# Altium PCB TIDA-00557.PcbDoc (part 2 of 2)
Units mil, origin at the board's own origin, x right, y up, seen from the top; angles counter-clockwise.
Board outline 3556 x 3500 mil, 2 copper layers (Top Layer, Bottom Layer), stack 62 mil thick; 145 components, 107 nets, 402 pads, 185 vias.
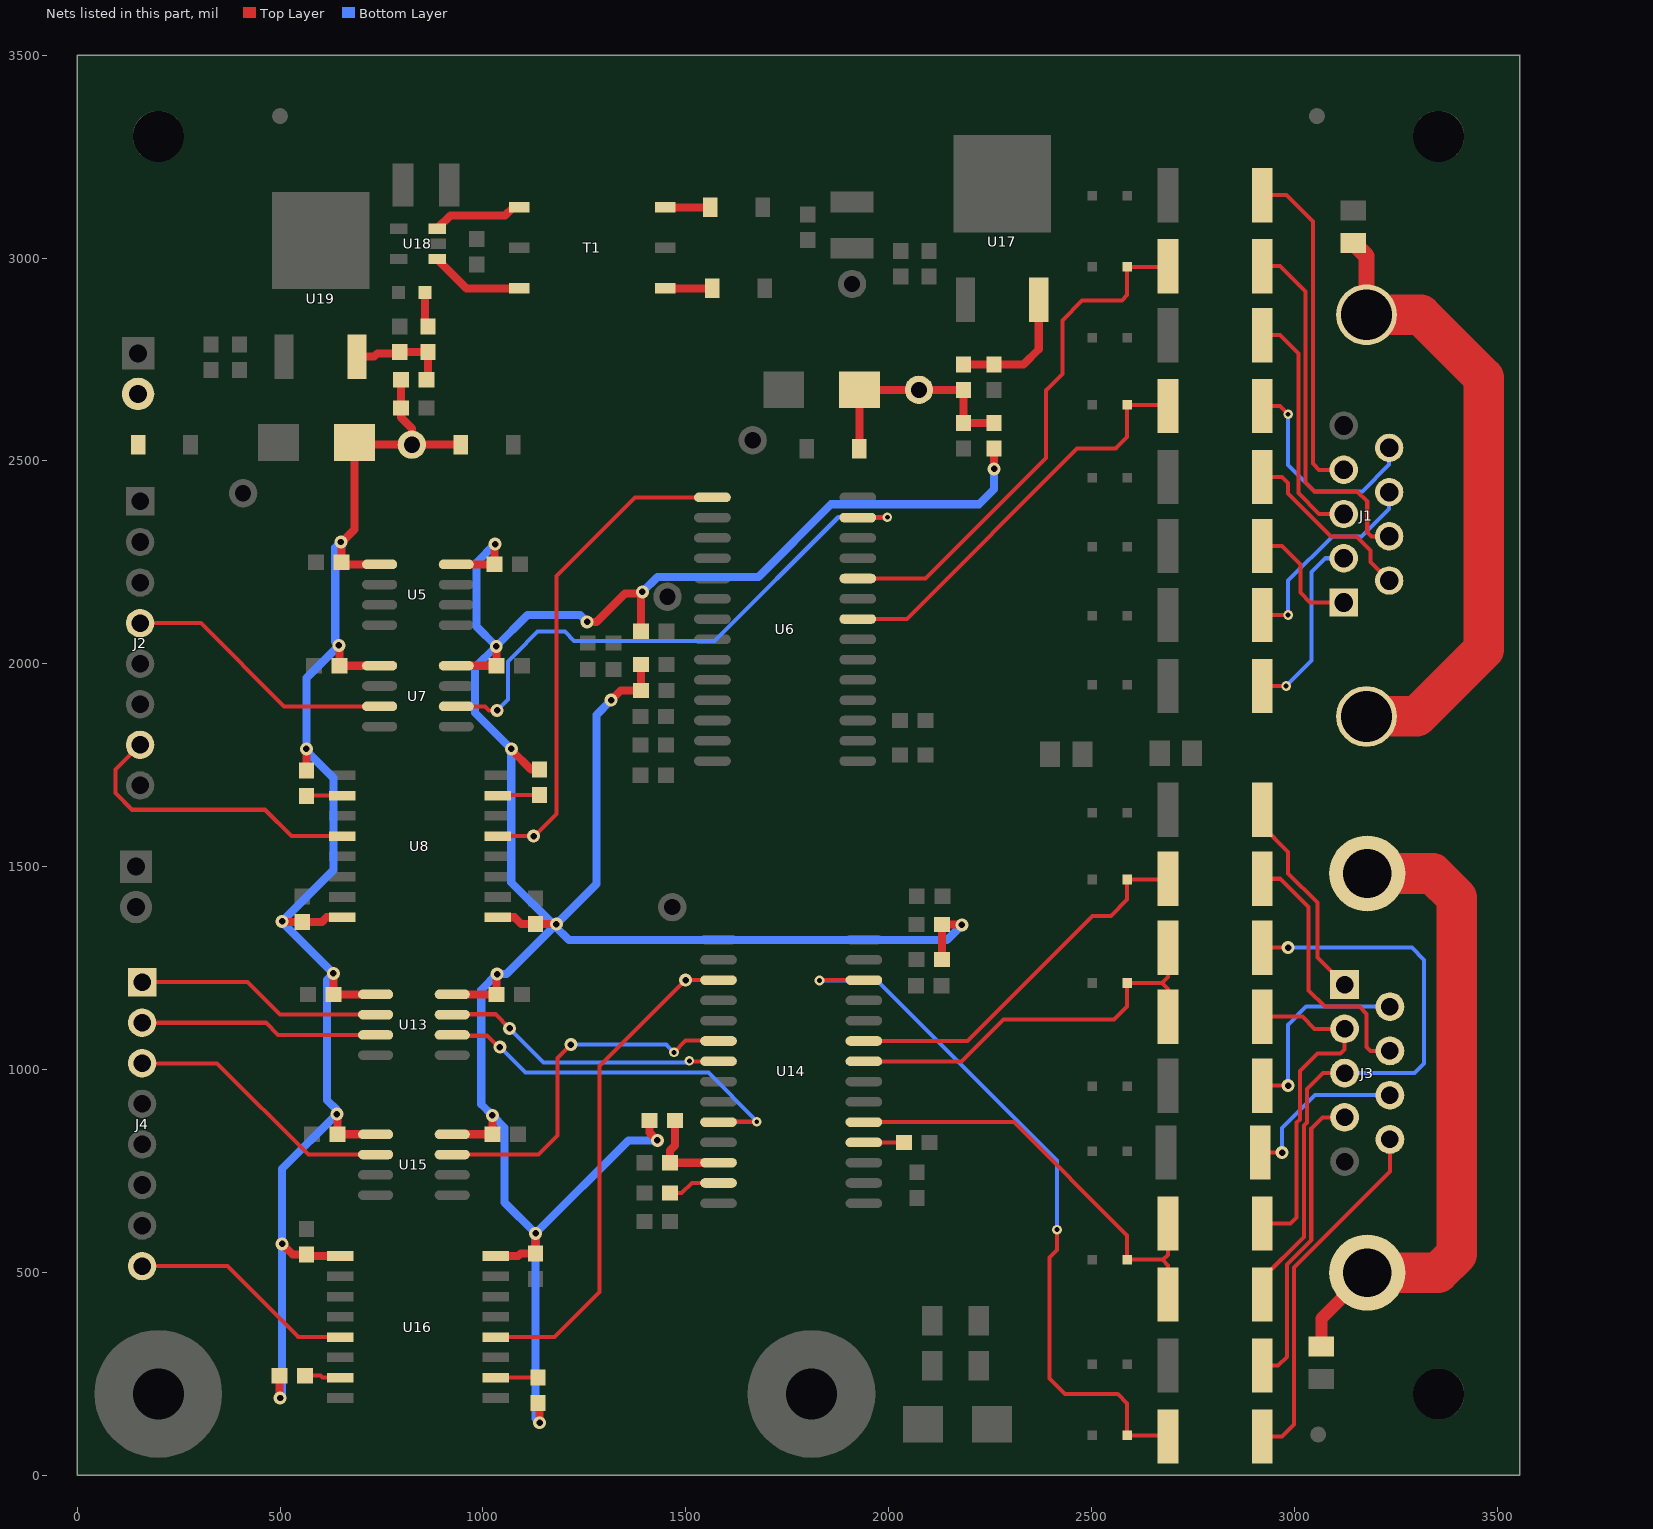
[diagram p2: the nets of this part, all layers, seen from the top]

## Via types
v1: diameter 32, hole 16, Top Layer to Bottom Layer, 163 vias
v2: diameter 24, hole 12, Top Layer to Bottom Layer, 22 vias

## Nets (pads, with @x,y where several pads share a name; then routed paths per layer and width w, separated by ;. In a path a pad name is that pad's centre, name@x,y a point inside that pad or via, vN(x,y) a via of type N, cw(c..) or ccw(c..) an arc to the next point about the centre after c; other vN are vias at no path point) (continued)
NetC18_1: C18.1 U14.4 | length 99.4
  Top Layer w10: U14.4@1939.13,820 C18.1@2038.5,820
NetC19_1: C19.1 U14.27 | length 129.7
  Top Layer w10: C19.1@1461.5,695 1490,695 1515,720 U14.27@1580.87,720
NetC20_1: C20.1 R50.1 U14.26 | length 228.3
  Top Layer w20: R50.1@1473.5,874 1473.5,812.5 1461.5,800.5 C20.1@1461.5,770 U14.26@1580.87,770
NetC27_1: C27.1 C31.1 D23.1 FB1.2 R17.1 TP1.1 | length 558.9
  Top Layer w20: D23.1@1927.47,2530 1928.5,2531.04 C27.1@1928.5,2675 TP1.1@2075,2675 FB1.2@2185,2675 C31.1@2185,2592.99 R17.1@2260,2592.99
NetC28_1: C28.1 FB1.1 U17.3 | length 322.3
  Top Layer w20: FB1.1@2185,2737.99 C28.1@2260,2737.99 2332.99,2737.99 2370.16,2775.16 U17.3@2370.16,2896.89
NetC34_1: C34.1 FB2.1 R18.2 U19.3 | length 249.6
  Top Layer w20: U19.3@690.16,2756.89 731.89,2756.89 740,2765 791.5,2765 C34.1@795,2768.5 R18.2@865,2768.5 865,2703.5 FB2.1@861.5,2700
NetD1_2: D1.2 T1.6 | length 110.7
  Top Layer w20: T1.6@1449.84,3125 D1.2@1560.53,3125
NetD2_2: D2.2 T1.4 | length 115.7
  Top Layer w20: T1.4@1449.84,2925 D2.2@1565.53,2925
NetD3_2: D3.2 J5.2 | length 0.8
  Top Layer w20: D3.2@150,2540.53 D3.2@150.53,2540
NetD4_2: D4.2 R18.1 | length 86.6
  Top Layer w20: D4.2@857.48,2915 857.48,2839.02 R18.1@865,2831.5
NetJ1_1: J1.1 R19.2 | length 299.4
  Top Layer w10: R19.2@2921.14,2290 2970,2290 3015,2245 3015,2175 3039,2151 J1.1@3122,2151
NetJ1_2: J1.2 R21.2 | length 459
  Top Layer w10: R21.2@2921.14,1945 2949.73,1945 v2(2980,1945)
  Bottom Layer w10: v2(2980,1945) 3043,2008 3043,2226 3077,2260 J1.2@3122,2260
NetJ1_3: J1.3 R23.2 | length 585.4
  Top Layer w10: R23.2@2921.14,2810 2965,2810 3010,2765 3010,2420.46 3061.46,2369 J1.3@3122,2369
NetJ1_4: J1.4 R25.2 | length 831
  Top Layer w10: R25.2@2921.14,3155 2981,3155 3046,3090 3046,2493 3061,2478 J1.4@3122,2478
NetJ1_6: J1.6 R20.2 | length 449.5
  Top Layer w10: R20.2@2921.14,2460 2970,2460 2985,2445 2985,2420 3091,2314 3153,2314 3187.89,2279.11 3187.89,2251.11 J1.6@3234,2205
NetJ1_7: J1.7 R22.2 | length 908.6
  Top Layer w10: R22.2@2921.14,2980 2965,2980 3028,2917 3028,2447 3050,2425 3155,2425 3180,2400 3180,2324 3190,2314 J1.7@3234,2314
NetJ1_8: J1.8 R24.2 | length 512.2
  Top Layer w10: R24.2@2921.14,2120 v2(2985,2120)
  Bottom Layer w10: v2(2985,2120) 2985,2205 3094,2314 3166.12,2314 3234,2381.88 J1.8@3234,2423
NetJ1_9: J1.9 R26.2 | length 541.5
  Top Layer w10: R26.2@2921.14,2635 2965,2635 v2(2985,2615)
  Bottom Layer w10: v2(2985,2615) 2985,2490 3050,2425 3168.12,2425 3234,2490.88 J1.9@3234,2532
NetJ1_10: J1.10 J1.11 L1.1 | length 1570.8
  Top Layer w40: L1.1@3146,3037 3178,3005 J1.10@3178,2860
  Top Layer w100: J1.11@3178,1870 3302,1870 3467,2035 3467,2705 3312,2860 J1.10@3178,2860
NetJ3_1: J3.1 R31.1 | length 514.9
  Top Layer w10: R31.1@2921.14,1640 2921.14,1599.86 2985,1536 2985,1483 3057,1411 3057,1276.19 J3.1@3124.08,1209.11
NetJ3_4: J3.4 R35.1 | length 750.5
  Top Layer w10: R35.1@2921.14,270 2960,270 2981.65,291.65 2981.65,519.19 3042,579.54 3042,854 3069.95,881.95 J3.4@3124.08,881.95
NetJ3_6: J3.6 R32.1 | length 483.2
  Top Layer w10: R32.1@2921.14,960 v1(2985,960)
  Bottom Layer w10: v1(2985,960) 2985,1110 3029.58,1154.58 J3.6@3235.89,1154.58
NetJ3_7: J3.7 R33.1 | length 658.7
  Top Layer w10: R33.1@2921.14,1470 2965,1470 3035,1400 3035,1195 3075.42,1154.58 3160.42,1154.58 3178,1137 3178,1055 3187.47,1045.53 J3.7@3235.89,1045.53
NetJ3_8: J3.8 R34.1 | length 413.5
  Top Layer w10: R34.1@2916.14,795 v1(2970,795)
  Bottom Layer w10: v1(2970,795) 2970,855 3051.47,936.47 J3.8@3235.89,936.47
NetJ3_9: J3.9 R36.1 | length 891.4
  Top Layer w10: R36.1@2921.14,95 2970,95 2999.65,124.65 2999.65,511.74 3235.89,747.98 J3.9@3235.89,827.42
NetJ3_10: J3.10 J3.11 L2.1 | length 1592.7
  Top Layer w30: L2.1@3067,317 3067,386.09 J3.11@3179.98,499.07
  Top Layer w100: J3.11@3179.98,499.07 3355.07,499.07 3401,545 3401,1423 3341.07,1482.93 J3.10@3179.98,1482.93
NetR7_1: R7.1 U8.7 | length 115.9
  Top Layer w10: U8.7@1024.13,1676.5 R7.1@1140,1676.5
NetR8_1: R8.1 U8.10 | length 101.5
  Top Layer w10: R8.1@565,1673.5 566.5,1675 U8.10@665.87,1675
NetR15_1: R15.1 U16.10 | length 117.1
  Top Layer w10: U16.10@1019.13,240 1135.5,240 R15.1@1136,240.5
NetR16_1: R16.1 U16.7 | length 101.4
  Top Layer w10: R16.1@561.5,245 600,245 605,240 U16.7@660.87,240
NetT1_1: T1.1 U18.3 | length 224.5
  Top Layer w20: U18.3@887.24,3072.4 919.84,3105 1055,3105 1075,3125 T1.1@1090,3125
NetT1_3: T1.3 U18.1 | length 232.8
  Top Layer w20: U18.1@887.24,2997.6 959.84,2925 T1.3@1090,2925
RI_IN: D13.1 R26.1 U6.8 | length 1031.3
  Top Layer w10: U6.8@1924.13,2110 2045,2110 2465,2530 2560,2530 2588.31,2558.31 D13.1@2588.31,2637.99 2685.87,2637.99 R26.1@2688.86,2635
RI_IN_1: U6.15 U8.5 | length 1235
  Top Layer w10: U8.5@1024.13,1575 v1(1125,1575) ; v1@1119,1581 1133,1581 1181,1629 1181,2216 1375,2410 U6.15@1565.87,2410
RI_OUT: D22.1 R36.2 U14.12 | length 1820.1
  Top Layer w10: v2(1830,1219) 1831,1220 U14.12@1939.13,1220 ; v2(2415,605) 2415,554.47 2397,536.47 2397,238 2435,200 2565,200 2588.31,176.69 D22.1@2588.31,97.99 2685.87,97.99 R36.2@2688.86,95
  Bottom Layer w10: v2(1830,1219) 1971,1219 2415,775 v2(2415,605)
RI_OUT_1: U14.17 U16.12 | length 1252.3
  Top Layer w10: U16.12@1019.13,340 1176.54,340 1288,451.46 1288,1008 v1(1500,1220) U14.17@1580.87,1220
RIIN: J2.7 U8.12 | length 759.8
  Top Layer w10: J2.7@155,1800 94,1739 94,1681.46 135.46,1640 462.83,1640 527.83,1575 U8.12@665.87,1575
RIOUT: J4.8 U16.5 | length 573.4
  Top Layer w10: J4.8@160,515 370,515 545,340 U16.5@660.87,340
RTS_IN: D20.1 R33.2 U14.9 | length 944.5
  Top Layer w10: U14.9@1939.13,1070 2195,1070 2503,1378 2548,1378 2588.31,1418.31 D20.1@2588.31,1467.99 2686.85,1467.99 R33.2@2688.86,1470
RTS_IN_1: U14.20 U15.7 | length 899.4
  Top Layer w10: U15.7@924.49,790 1137,790 1184,837 1184,1028 v1(1217,1061) ; v2(1471,1042) 1500,1071 U14.20@1579.87,1071
  Bottom Layer w10: v1(1217,1061) 1452,1061 v2(1471,1042)
RTS_OUT: D9.1 R22.1 U6.10 | length 1299.9
  Top Layer w10: U6.10@1924.13,2210 2091.46,2210 2388,2506.54 2388,2674 2428.46,2714.46 2428.46,2846.46 2477,2895 2575,2895 2588.31,2908.31 D9.1@2588.31,2977.99 2686.85,2977.99 R22.1@2688.86,2980
RTS_OUT_1: U6.13 U7.6 | length 1410.8
  Top Layer w10: U7.6@934.49,1895 1005,1895 1015,1885 v1(1035,1885) ; U6.13@1924.13,2361 v2(1997,2361)
  Bottom Layer w10: v1(1035,1885) 1062,1912 1062,2005.53 1080,2023.53 1080,2024 1135,2079 1202,2079 1225,2056 1571,2056 1876,2361 v2(1997,2361)
RTSIN: J4.3 U15.2 | length 668.7
  Top Layer w10: J4.3@160,1015 345,1015 570,790 U15.2@735.51,790
RTSOUT: J2.4 U7.3 | length 675.4
  Top Layer w10: J2.4@155,2100 305,2100 510,1895 U7.3@745.51,1895
RX_IN: J3.2 R27.2 R29.2 | length 853.8
  Top Layer w10: R27.2@2921.14,620 2991,620 3006,635 3006,868.91 3014,876.91 3014,996 3057.43,1039.43 3114.43,1039.43 3124.08,1049.08 J3.2@3124.08,1100.06 3049.94,1100.06 3020,1130 R29.2@2921.14,1130
RX_IN_1: U13.7 U14.21 | length 709.8
  Top Layer w10: U13.7@924.49,1135 927.49,1138 929.49,1136 1031,1136 v1(1066,1101) ; v2(1509,1021) 1510,1020 U14.21@1580.87,1020
  Bottom Layer w10: v1(1066,1101) 1150,1017 1505,1017 v2(1509,1021)
RX_IN_T: D16.1 R29.1 R30.1 U14.8 | length 1030.9
  Top Layer w10: U14.8@1939.13,1020 2180,1020 2283,1123 2556,1123 2588.31,1155.31 D16.1@2588.31,1212.99 2674.01,1212.99 ; R29.1@2688.86,1130 2688.86,1198.14 2674.01,1212.99 ; R30.1@2688.86,1300 2688.86,1227.84 2674.01,1212.99
RXIN: J4.1 U13.2 | length 608.6
  Top Layer w10: J4.1@160,1215 420,1215 500,1135 U13.2@735.51,1135
TX_OUT: J3.3 R28.2 R30.2 | length 1533.3
  Top Layer w10: R28.2@2921.14,445 2921.14,484.14 3024,587 3024,861.46 3032,869.46 3032,952 3071,991 J3.3@3124.08,991 ; R30.2@2921.14,1300 v1(2985,1300)
  Bottom Layer w10: v1(2985,1300) 3290,1300 3320,1270 3320,1015 3296,991 J3.3@3124.08,991
TX_OUT_1: U13.6 U14.24 | length 934.9
  Top Layer w10: U13.6@924.49,1085 926.49,1083 1010,1083 1038,1055 v1(1042,1055) ; U14.24@1580.87,870 1581.87,871 v2(1675,871)
  Bottom Layer w10: v1(1042,1055) 1105,992 1556,992 1675,873 v2(1675,871)
TX_OUT_T: D17.1 R27.1 R28.1 U14.5 | length 1101.7
  Top Layer w10: U14.5@1939.13,870 2309,870 2588.31,590.69 D17.1@2588.31,530.99 2675.01,530.99 ; R28.1@2686.85,442.99 R28.1@2688.86,445 2688.86,517.14 2675.01,530.99 ; R27.1@2688.86,620 2688.86,542.86 2676.99,530.99 2675.01,530.99
TXOUT: J4.2 U13.3 | length 587.9
  Top Layer w10: J4.2@160,1115 465,1115 495,1085 U13.3@735.51,1085
VCC1: C1.1 C4.1 C10.1 C12.1 C16.1 C21.1 C35.1 C36.1 D5.1 FB2.2 R8.2 R16.2 TP3.1 U5.1 U7.1 U8.16 U13.1 U15.1 U16.1 | length 4092.2
  Top Layer w20: R16.2@498.5,245 498.5,191.5 v1(500,190) ; v1(505,570) 531.5,543.5 C21.1@565,543.5 568.5,540 U16.1@660.87,540 ; v1(505,1365) 506.5,1363.5 C10.1@555,1363.5 603.5,1363.5 615,1375 U8.16@665.87,1375 ; R8.2@565,1736.5 v1(565,1790) ; v1(631.5,1236.5) C12.1@631.5,1185 U13.1@735.51,1185 ; v1(640,890) 641.5,888.5 C16.1@641.5,840 U15.1@735.51,840 ; v1(645,2045) 646.5,2043.5 C4.1@646.5,1995 U7.1@745.51,1995 ; U5.1@745.51,2245 656.5,2245 C1.1@651.5,2250 651.5,2298.5 683.5,2330.51 C35.1@683.5,2545 688.5,2540 TP3.1@825,2540 ; FB2.2@798.5,2700 C36.1@798.5,2630 798.5,2606.5 825,2580 TP3.1@825,2540 ; D5.1@945.53,2540 TP3.1@825,2540
  Bottom Layer w20: v1(500,190) 505,195 v1(505,570) 505,755 v1(640,890) 640,900 616,924 616,1221 v1(631.5,1236.5) 505,1362.99 v1(505,1365) 631.5,1491.5 631.5,1718.42 565,1784.92 v1(565,1790) 565,1965 v1(645,2045) 636,2054 636,2286 v1(650,2300)
VCC2: C2.1 C5.1 C11.1 C13.1 C17.1 C22.1 R1.2 R2.2 R7.2 R9.2 R10.2 R15.2 R17.2 R50.2 R51.1 U5.8 U7.8 U8.1 U13.8 U15.8 U16.16 | length 7489.5
  Top Layer w20: U15.8@924.49,840 C17.1@1023.5,840 v1(1023.5,886.5) ; U13.8@924.49,1185 C13.1@1033.5,1185 1033.5,1233.5 v1(1035,1235) ; U7.8@934.49,1995 C5.1@1033.5,1995 1033.5,2042.5 v1(1033,2043) ; U5.8@934.49,2245 C2.1@1028.5,2245 1028.5,2293.5 v1(1030,2295) ; U16.16@1019.13,540 1087,540 1093.5,546.5 C22.1@1130,546.5 v1(1130,596) ; U8.1@1024.13,1375 1078,1375 1094.5,1358.5 C11.1@1130,1358.5 1180.5,1358.5 v1(1181,1358) ; v1(1070,1790) 1070,1787.8 1118.3,1739.5 R7.2@1140,1739.5 ; R15.2@1136,177.5 1140,173.5 v1(1140,129) ; v1(1257,2103) 1280,2103 1350.5,2173.5 1389.5,2173.5 R2.2@1389.5,2080 ; v1(1316,1910) 1340,1934 R51.1@1389.5,1934 R1.2@1389.5,1998 ; R50.2@1410.5,874 1410.5,844.5 v1(1430,825) ; R9.2@2131.5,1271 R10.2@2131.5,1357 2180,1357 v1(2181,1356) ; v1(2260,2480) R17.2@2260,2530
  Bottom Layer w20: v1(1030,2295) 984,2249 984,2092 v1(1033,2043) ; v1(1140,129) 1130,139 v1(1130,596) ; v1@1173,1358 1070,1461 v1(1070,1790) 981,1879 981,1991 v1(1033,2043) ; v1@1177,1354 1212,1319 2144,1319 v1(2181,1356) ; v1(1257,2103) 1240,2120 1110,2120 v1(1033,2043) ; v1(1316,1910) 1280,1874 1280,1457 1058,1235 v1(1035,1235) 996,1196 996,914.01 v1(1023.5,886.5) 1053.76,856.24 1053.76,672.24 v1(1130,596) ; v1(1393,2177) 1430,2214 1679,2214 1858,2393 2223,2393 2260,2430 v1(2260,2480) ; v1(1430,825) 1359,825 v1(1130,596)
pads on no net: FID1.1 FID2.1 FID3.1 H2.1 H3.1 H5.0 H6.0 H7.0 H8.0 H9.1 H10.0 LBL1.0 U6.20 U14.16

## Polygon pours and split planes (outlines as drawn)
GND1 on Top Layer "Top Layer-No Net" (solid, remove dead copper, pour order 26): 96,1555 211,1555 216,1550 216,1346 205,1335 88,1335 79,1344 79,1550 84,1555
NetD3_2 on Top Layer "Top Layer-No Net" (solid, remove dead copper, pour order 18): 90,2709 191,2709 199,2701 199,2491 193,2485 92,2485 78,2499 78,2698 89,2709
+5V on Top Layer "Top Layer-No Net" (solid, pour order 21): 480,2815 535,2815 545,2805 545,2695 535,2685 515,2665 445,2665 402.43,2665 371.74,2635 330,2593.26 330,2500 315,2485 265,2485 245,2505 245,2731.26 256.3,2742.56 260.24,2746.5 268.11,2746.5 461.5,2746.5 470,2755 470,2805
GND1 on Top Layer "Top Layer-No Net" (solid, pour order 24): 499,3245 827,3245 840,3232 840,3210 840,3135 820,3115 820,2980 810,2970 730,2970 725,2965 725,2925 715,2915 490,2915 475,2930 475,2950 475,3221
VCC1 on Top Layer "Top Layer-No Net" (solid, remove dead copper, pour order 22): 760.2,2727.2 819.8,2727.2 823,2724 828,2719 828,2601 838,2591 849,2591 963,2591 974,2580 974,2455 968,2449 629,2449 614,2464 614,2609 633,2628 637,2628 748,2628 758,2638 758,2701 758,2725
+6V_VDC on Top Layer "Top Layer-No Net" (solid, remove dead copper, pour order 16): 1664,3155 1664,2858 1696,2826 2256,2826 2268,2838 2268,2963 2254,2977 2252,2977 2097,2977 1978,2977 1975,2980.84 1975,2997 1975,3051 1962,3064 1759,3064 1756,3067 1735,3088 1735,3134 1735,3157 1728,3164 1727,3165 1674,3165
GND_EARTH on Top Layer "Top Layer-No Net" (solid, remove dead copper, pour order 27): 2135,410 2135,75 2130,70 1885,70 1674,70 1650,94 1650,394 1671,415 2135,415
GND3 on Top Layer "Top Layer-No Net" (solid, remove dead copper, pour order 28): 2452.5,1845 2452.5,1705 2462.5,1695 2677.5,1695 2692.5,1710 2692.5,1845 2682.5,1855 2462.5,1855 2452.5,1845
GND3 on Top Layer "Top Layer-No Net" (solid, remove dead copper, pour order 30): 2195,420 2195,60 2225,30 2420,30 2440,50 2440,400 2415,425 2200,425 2195,420
GND2 on Top Layer "Top Layer-No Net" (solid, remove dead copper, pour order 29): 1630.83,2441.3 1630.83,579.17 1690,520 2685,520 2840,365 3495,365 3529,399 3529,3402 3501,3430 1890,3430 1845,3385 1845,3121.85 1856.85,3110 1980,3110 2010,3080 2010,3005 2015,3000 2270,3000 2300,2970 2300,2570 2290,2560 1835,2560 1810,2585 1810,2720 1795,2735 1650,2735 1630,2715
GND2 on Bottom Layer "Top Layer-No Net" (solid, remove dead copper, pour order 17): 1404,3467 3471,3467 3514,3424 3514,375 3501,362 2727,362 2706,383 2706,3219 2691,3234 2405,3234 2375,3204 2375,506 2368,499 1648,499 1589,440 1589,110.45 1533.55,55 937,55 916.68,75.32 916.68,2281.68 917,2282 916.68,2282.32 916.68,2288.13 966.55,2338 1222,2338 1354.03,2470.03 1354.03,3417.03
GND3 on Bottom Layer "Top Layer-No Net" (solid, remove dead copper, pour order 20): 3152,284 3162,274 3162,183 3151,172 2331,172 2305,198 2305,375 2314,384 2611,384 2651,344 2651,290 2657,284
GND3 on Bottom Layer "Top Layer-No Net" (solid, remove dead copper, pour order 23): 2434,3129 2444,3119 3170,3119 3180,3129 3180,3212 3171,3221 2441,3221 2434,3214
GND1 on Bottom Layer "Top Layer-No Net" (solid, remove dead copper, pour order 25): 78,3445 1081,3445 1152,3374 1152,2491 1104,2443 844,2443 811,2410 809,2408 758,2357 758,55 66,55 55,66 55,3422
GND3 on Bottom Layer "Top Layer-No Net" (solid, remove dead copper, pour order 19): 2433,3160 2456.49,3183.49 2484.96,3183.49 2650.51,3183.49 2669,3165 2672,3162 2672,3041 2672,95 2657,80 2650,73 2514,73 2216,73 2208,81 2208,91 2208,394 2208,409 2218,419 2223,424 2326,424 2327,425 2395,425 2417,425 2427,435 2427,3090 2427,3154

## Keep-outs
Keep-Out Layer:
  lines w6: 10,10 3546,10 3546,3490 10,3490 10,10
  text ".Layer_Name" at 577,-858.49 h60
Multi-Layer:
  circle w10: c3356,200 r100
  circle w10: c203,3301 r100
  circle w10: c3352,3304 r100

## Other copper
Top Layer:
  pour cut-out: 3193,3249 3222.66,3249 3228,3243.66 3228,3224 3197,3224 3193,3228
  pour cut-out: 2416.96,1695 2416.96,1574.96 2386,1544 2386,799 2460,725 2460,390 2482,368 3498,368 3508,378 3508,1591 3501.7,1597.3 3072.7,1597.3 2982,1688 2982,1735 2976,1741 2711.57,1741 2692.5,1721.93 2648.27,1721.93 2648.27,1695.28 2647.99,1695
  pour cut-out: 1969,2269 1969,1901 2594,1901 2639,1856 2712,1856 2723,1845 3037,1845 3038,1844 3038,1780 3065,1753 3509,1753 3509,2981 3207,2981 3200,2988 3200,3248 2626,3248 2626,3198 2400,3198 2400,2485 2184,2269
  pour cut-out: 2424,1695.53 2423.47,1695 2442,1695 2442,1860.55 2440.55,1862 2424,1862
  pour cut-out: 2723,1845 2723,1741 2708,1741 2708,1845
  pour cut-out: 1869,1348 1868,1347 1868,656 1877,647 1982,647 2026.5,691.5 2026.5,1318.5 1997,1348
  pour cut-out: 1851,2432 1850,2431 1850,1740 1859,1731 1947,1731 1956,1740 1956,2421 1945,2432
  pour cut-out: 1616.7,1347.64 1647.36,1347.64 1655,1340 1655,550 1609.2,550
  pour cut-out: 2400,3198 2627,3198 2627,3065.23 2400,3065.23
  text ".Layer_Name" at 577,-858.49 h60
Bottom Layer:
  pour cut-out: 2420,3249 3211,3249 3211,3084 2715,3084 2707,3076 2706,3077 2706,3103.71 2706.29,3104 3174.98,3104 3194.13,3123.15 3194.13,3217.85 3175.98,3236 2407,3236
  pour cut-out: 2932,2655 3011,2655 3045,2621 3045,1881 2923,1881 2923,2646
  pour cut-out: 3089,2984 3090,2983 3509,2983 3509,1759 3505,1755 3063,1755 3038,1780 3038,2552 3040,2554 3167,2554 3187,2574 3187,2651 3165,2673 3165,2699 3085,2699 3085,2980
  pour cut-out: 3071,1597.3 3073.7,1600 3507.67,1600 3507.67,377.67 3496,366 3450,366 3449,365 3186,365 3186,1283 3127,1283 3096,1284 3081,1283 3066,1285 3068,1401 3068,1598 3070,1600
  pour cut-out: 2102.5,1112.5 2110,1120 2435,1120 2435,780 2430,775 2400,805 2235,805 2235,980
  pour cut-out: 2948,1339 2937,1339 2936,1338 2936,763 2937,762 3020,762 3021,763 3021,815 3176,815 3176,756 3317,756 3319,758 3319,815 3356,815 3357,816 3357,1336 3353,1340 2949,1340
  pour cut-out: 3020,762 3079,762 3080,761 3080,814 3081,815 3166,815 3166,757 3167,756 3176,756 3176,815 3021,815
  text ".Layer_Name" at 577,-858.49 h60
Multi-Layer:
  pour cut-out: 3038,1581.97 3057,1582 3079,1583 3079,1606 3050,1605 3050,1881 3038,1881
  pour cut-out: 3319,1267 3319,811 2971,811 2971,1267
  pour cut-out: 3187,2595 3145,2553 3187,2553

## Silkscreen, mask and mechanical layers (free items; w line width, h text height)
Top Overlay:
  circle w6: c1273,2594 r30
  circle w6: c1247,2191 r30
  circle w10: c652,577 r12.37
  circle w10: c720,876 r12.37
  circle w10: c701,1221 r12.37
  circle w10: c1025,1339 r12.37
  circle w10: c700,2027 r12.37
  circle w10: c736,2283 r12.37
  circle w10: c1940,634 r13.34
  circle w10: c1926,1723 r13.34
  circle w6: c929,2995 r8.94
  lines w6: 735,3211 750,3196 750,3089 762,3077 ; 896,2648 901,2648 913,2660 1058,2660 ; 935,2745 910,2745 ; 1169,2356 1156,2356 1155,2357 1155,2369 1155,2539 1157,2541 1173,2541 ; 1270,1906 1204,1906 1203,1907 1203,2118 1203,2126 1206,2129 1387,2129 ; 1379,2548 1401,2548 1402,2547 1402,2363 1401,2362 1380,2362 ; 1490,1900 1508,1900 1513,1905 1513,1926 ; 1496,2108 1506,2108 1509,2105 1509,1973 ; 2148,2757 2148,2485 2161,2485 ; 2169,2180 2142,2180 2140,2182 2140,2417 2168,2417 2169,2418 ; 2177,2490 2177,2451 2168,2460 2189,2460 2180,2451 ; 2249,2184 2270,2184 2271,2185 2271,2429 2270,2430 2253,2430 ; 2286,2778 2331,2778 2341,2778 2342,2777 2342,2489 2341,2490 2327,2490 ; 2953,836 2983,836 2992,845 ; 2953,2075 2956,2075 2975,2056 ; 2956,2613 2957,2613 2965,2621 ; 2957,1889 2966,1889 2979,1876 ; 2961,1334 2982,1334 2995,1347 ; 2967,908 2979,908 2995,924 ; 910,2745 915,2750 915,2740 910,2745
  text "A" at 1261,2574 h40
  text "A" at 1235,2171 h40
  text "TIDA-00557-A0" at 374,59 h40
  text ".Layer_Name" at 577,-858.49 h40
Bottom Overlay:
  text ".Layer_Name" at 577,-858.49 h35
Top Paste:
  text ".Layer_Name" at 577,-858.49 h60
Bottom Paste:
  text ".Layer_Name" at 577,-858.49 h60
Top Solder:
  text ".Layer_Name" at 577,-858.49 h60
  text ".Layer_Name" at 577,-858.49 h60
Bottom Solder:
  text ".Layer_Name" at 577,-858.49 h60
Drill Guide:
  text ".Layer_Name" at 577,-858.49 h60
M1 Board Outline:
  the board outline again, w10
M2 Board Dimensions:
  rectangle: -0.5,-285.5 124.5,-160.5
  rectangle: 124.5,-410.5 499.5,-285.5
  lines w7: -0.5,-285.5 999.5,-285.5 ; 124.5,-410.5 124.5,-160.5 ; 249.5,-410.5 249.5,-160.5 ; 499.5,-410.5 499.5,-160.5 ; 749.5,-410.5 749.5,-160.5 ; -0.5,-410.5 999.5,-410.5 999.5,-160.5 -0.5,-160.5 -0.5,-410.5
  lines w10: -0.5,-475.5 -0.5,-455.5 ; 59.5,-485.5 -0.5,-465.5 ; 59.5,-445.5 -0.5,-465.5 ; 223.58,-465.5 -0.5,-465.5 ; 775.42,-465.5 999.5,-465.5 ; 939.5,-485.5 999.5,-465.5 ; 939.5,-445.5 999.5,-465.5 ; 999.5,-475.5 999.5,-455.5
  text "1000 (mil)" at 233.58,-501.49 h60
M3 3D STEP Top:
  text ".Layer_Name" at 577,-858.49 h60
M4 3D STEP Bottom:
  text ".Layer_Name" at 577,-858.49 h60
M5 Assembly Top:
  circle w10: c508,2768 r16.49
  circle w10: c2131,2890 r16.49
  circle w6: c929,2995 r8.94
  lines w6: 873,2886 873,2885 879,2879 938,2879 ; 886,2916 902,2916 ; 902,2936 902,2898 902,2916 ; 921,2897 902,2916 ; 924,2897 924,2907 924,2927 924,2938 902,2916 ; 926,2916 947,2916
  lines w10: -292,-930.17 6308,-930.17 ; -292,-726.83 6310,-726.83 ; -292,-523.5 -292,-1133.5 3713,-1133.5 6310,-1133.5 6310,-523.5 -291.5,-523.5 -291.5,-1133.5 1284,-1133.5 ; 2173,-1133.5 2173,-523.5 ; 3735,-726 3735,-522.67 ; 4280,-726.83 4280,-523.5 ; 4902,-1140 4902,-937.17
  text "COMPONENTS MARKED 'DNP' SHOULD NOT BE POPULATED." at 1153.5,-318.5 h40
  text "ASSEMBLY VARIANT:" at 1153,-434 h40
  text ".VariantName" at 2189,-434 h40
  text "PCB VIEWED FROM TOP SIDE" at -228.5,-655.67 h40
  text "BOARD #:" at 2248,-655.67 h40
  text "TIDA-00557" at 2736,-656 h40
  text "SVN REV:" at 4476,-655.67 h40
  text ".VersionControl_RevNumber" at 4982,-655.67 h40
  text "REV: A0" at 3805,-660 h40
  text "Assembly top" at 590,-855 h40
  text "LAYER NAME" at -228.5,-858.49 h40
  text "PLOT NAME =" at -228.5,-1064.34 h40
  text ".plot_File_Name" at 577,-1064.34 h40
  text "GENERATED    :" at 2250,-1064.34 h40
  text ".Print_Date" at 3119.5,-1064.34 h40
  text ".Print_Time" at 3848.5,-1064.34 h40
  text "TEXAS INSTRUMENTS" at 5113,-1064.34 h40
M6 Assembly Bottom:
  lines w10: -292.5,-727.33 6309.5,-727.33 ; -290.5,-930.67 6309.5,-930.67 ; 1115.5,-1140.5 1115.5,-937.67 ; 1737.5,-727.33 1737.5,-524 ; 2236,-723 2236,-519.67 ; 3844.5,-1134 3844.5,-524 ; 4733.5,-1134 6309,-1134 6309,-524 -292.5,-524 -292.5,-1134 2304.5,-1134 6309.5,-1134 6309.5,-524
  text "COMPONENTS MARKED 'DNP' SHOULD NOT BE POPULATED." at 6102,-318 h60
  text ".VariantName" at 5058,-434 h60
  text "ASSEMBLY VARIANT:" at 6097,-434 h60
  text "REV: A0" at 2173,-655 h60
  text ".VersionControl_RevNumber" at 1035.5,-656.17 h60
  text "SVN REV:" at 1541.5,-656.17 h60
  text "BOARD #:" at 3769.5,-656.17 h60
  text "PCB VIEWED FROM BOTTOM SIDE" at 6246,-656.17 h60
  text "TIDA-00557" at 3247,-663 h60
  text "Assembly Bottom" at 1760,-856 h60
  text "IGNORE ->" at 2547.85,-858.49 h60
  text "TEXAS INSTRUMENTS" at 904.5,-1064.84 h60
  text ".Print_Time" at 2169,-1064.84 h60
  text ".Print_Date" at 2898,-1064.84 h60
  text "GENERATED    :" at 3767.5,-1064.84 h60
  text ".plot_File_Name" at 5440.5,-1064.84 h60
  text "PLOT NAME =" at 6246,-1064.84 h60
M9 Title Sheet:
  drawing of 57 lines, arcs and shapes, not listed
  text "1" at 739.84,8036.5 h70
  text "2" at 3235.5,8036.5 h70
  text "3" at 5724.84,8036.5 h70
  text "4" at 8231.51,8036.5 h70
  text "5" at 10730.5,8036.5 h70
  text "6" at 13235.5,8036.5 h70
  text "A" at -416.5,6893.5 h70
  text "A" at 14383.5,6893.5 h70
  text "B" at -416.5,4513.5 h70
  text "B" at 14383.5,4513.5 h70
  text "C" at -416.5,2138.5 h70
  text "C" at 14383.5,2138.5 h70
  text "PROJECT TITLE:" at 11343.5,277.5 h45
  text ".PRJ_Title" at 11855,179 h60
  text "DESIGNED FOR:" at 11343.5,-23.5 h45
  text ".PRJ_Customer" at 11393.5,-163.5 h60
  text "D" at -416.5,-231.5 h70
  text "D" at 14383.5,-231.5 h70
  text "FILE NAME:" at 11343.5,-323.5 h45
  text "TIDA-00557" at 11750,-403 h60
  text "Texas Instruments (TI) and/or its licensors do not warrant the accuracy or completeness of this specification" at 6374,-605.34 h45
  text "ENGINEER:" at 11343.5,-613.5 h45
  text "LAYOUT BY:" at 12848.5,-613.5 h45
  text "Manjunatha T N" at 13233,-708 h60
  text "or any information contained therein. TI and/or its licensors do not warrant that this design will meet" at 6329.01,-718 h45
  text ".PRJ_Engineer" at 11646,-720 h60
  text "the specifications, will be suitable for your application or fit for any particular purpose, or will operate in" at 6329.01,-830.67 h45
  text "ALTIUM DESIGNER VERSION:" at 12848.5,-923.5 h45
  text "an implementation. TI and/or its licensors do not warrant that the design is production worthy. You should" at 6329.01,-943.33 h45
  text "completely validate and test your design implementation to confirm the system functionality for your application." at 6374,-1056 h45
  text ".print_Scale" at 11393.5,-1056.83 h70
  text ".Application_BuildNumber" at 12899,-1056.83 h70
  text "1" at 739.84,-1263.5 h70
  text "2" at 3235.5,-1263.5 h70
  text "3" at 5724.84,-1263.5 h70
  text "4" at 8231.51,-1263.5 h70
  text "5" at 10730.5,-1263.5 h70
  text "6" at 13235.5,-1263.5 h70
M10 Fab Notes:
  drawing of 220 lines, arcs and shapes, not listed
  text "DESIGN INFORMATION" at 12381.02,6810 h60
  text "(REFER ALSO ARRAY/PANEL PROFILING INFORMATION)" at 12019.46,6648.29 h60
  text "BOARD SIZE" at 11333.46,6644 h60
  text "3556MIL" at 11795.78,6516.18 h60
  text "X" at 12301.46,6516.18 h60
  text "3500MIL" at 12532.78,6516.18 h60
  text "Number of Layers :" at 11726.46,6422 h60
  text "2" at 12821.27,6412 h60
  text "10" at 12795,6286 h60
  text "MIN. TRACK WIDTH:" at 11726.46,6283 h60
  text "MIL" at 12977.46,6283 h60
  text "8" at 12815,6159 h60
  text "MIN. CLEARANCE:" at 11726.46,6151 h60
  text "MIL" at 12977.46,6151 h60
  text "MIN. VIA PAD SIZE:" at 11726.46,6019 h60
  text "24" at 12792.71,6019 h60
  text "MIL" at 12977.46,6019 h60
  text "MINIMUM ANNULAR RING:" at 11726,5910 h60
  text "6MIL" at 12813,5901 h60
  text "EXTERNAL" at 13172,5875 h60
  text "PER" at 11597.23,5755 h60
  text "IPC-D-275 CLASS 2 LEVEL C" at 11817.23,5755 h60
  text "MIL, HOLES" at 13305.46,5642.71 h60
  text "+/-" at 12913,5642 h60
  text "+/-" at 13767,5642 h60
  text "REGISTRATION TOLERANCES:" at 11397.23,5637 h60
  text "METAL" at 12597,5637 h60
  text "5" at 13173.2,5637 h60
  text "3" at 14006.2,5637 h60
  text "MIL" at 14122.46,5637 h60
  text "IMPEDANCE CONTROLLED:NO" at 11604.46,5519 h60
  text "MATERIAL:" at 11332.46,5324.54 h60
  text "FR-4 High Tg" at 12318.9,5184.21 h60
  text "X" at 11606.46,5175.64 h60
  text "FR-408" at 11753.46,5175.64 h60
  text "OTHER" at 13241.46,5175.64 h60
  text "63 MIL (1.6mm) +/-10%" at 12073.56,5012.92 h60
  text "THICKNESS:" at 11407.23,5008.64 h60
  text "X" at 11945.4,5008.64 h60
  text "OTHER" at 13358.46,5008.64 h60
  text "TOLERANCE:" at 11407.23,4850.64 h60
  text "X" at 12246.53,4850.64 h60
  text "ANSI IPC-6012 TYPE 3 CLASS 2" at 12433.48,4850.64 h60
  text "OTHER +/-" at 12433.46,4694.64 h60
  text "BOW & TWIST:" at 11407.23,4537.64 h60
  text "X" at 12246.53,4537.64 h60
  text "ANSI IPC-6012 TYPE 3 CLASS 2" at 12433.48,4537.64 h60
  text "OTHER +/-" at 12433.46,4379.13 h60
  text "COPPER THICKNESS (FINISHED):" at 11332.46,4243.64 h60
  text "1.4MIL (1oz)" at 12212.46,4090.92 h60
  text "2MIL (1.4oz)" at 12979.46,4090.92 h60
  text "2.8MIL (2oz)" at 13706.46,4090.92 h60
  text "OUTER:" at 11689.46,4086.64 h60
  text "X" at 12084,4086 h60
  text "1.4MIL (1oz)" at 12212.46,3933.92 h60
  text "2.8MIL (2oz)" at 12979.46,3933.92 h60
  text "N/A" at 13706,3934.29 h60
  text "INNER SIGNAL:" at 11400.38,3929.64 h60
  text "DRILLING:" at 11332.46,3790.64 h60
  text "REFERENCE:" at 11407.23,3673.64 h60
  text "X" at 12055.46,3673.64 h60
  text "AS SHOWN" at 12242.46,3673.64 h60
  text "X" at 12956.46,3673.64 h60
  text "NC_DRILL FILES" at 13093.46,3673.64 h60
  text "PTH MIN COPPER THICKNESS:" at 11407.23,3515.64 h60
  text "X" at 12757.46,3515.64 h60
  text "1MIL" at 12894.46,3515.64 h60
  text "OTHER" at 13391.46,3515.64 h60
  text "BOARD FINISH:" at 11332.46,3356.64 h60
  text "SILKSCREEN:" at 11487.68,3238.64 h60
  text "X" at 12436.46,3238.64 h60
  text "TOP" at 12562.46,3238.64 h60
  text "BOTTOM" at 13073.46,3238.64 h60
  text "SILKSCREEN COLOR:" at 11486.01,3072.64 h60
  text "X" at 12433.75,3072.64 h60
  text "WHITE" at 12560.79,3072.64 h60
  text "OTHER" at 13071.79,3072.64 h60
  text "SOLDER RESIST COLOR:" at 11592.01,2921.64 h60
  text "GREEN" at 12286.79,2762.44 h60
  text "X" at 12049,2750 h60
  text "BLUE" at 12857,2744 h60
  text "OTHER" at 13306,2740 h60
  text "IMMERSION GOLD (ENIG)" at 12393.46,2553.92 h60
  text "ENEPIG" at 13731,2550.64 h60
  text "SURFACE FINISH:" at 11332.46,2549.64 h60
  text "X" at 12206.51,2549.64 h60
  text "IMM. TIN/SILVER OR EQUIV" at 11662,2392.64 h60
  text "OTHER" at 13093.46,2392.64 h60
  text "ARRAY/PANEL:" at 11332.46,2213.64 h60
  text "CUT AND TRIM PER MECH LAYER 1" at 12393.46,2209.35 h60
  text "N.C. ROUTE" at 12393.46,2057.64 h60
  text "X" at 13072.46,2057.64 h60
  text "V. SCORE" at 13259.46,2057.64 h60
  text "CERTIFICATION:" at 11332.46,1920.64 h60
  text "MATERIALS AND WORKMANSHIP FOR ALL PCBS" at 12057.46,1920.64 h60
  text "TO MEET OR EXCEED THE REQUIREMENTS OF:" at 12057.46,1822.64 h60
  text "X" at 11683.96,1686.13 h60
  text "ANSI IPC-A-600F CLASS ->" at 11822.96,1686.13 h60
  text "X" at 13462.02,1686.13 h60
  text "2" at 13580.96,1686.14 h60
  text "1" at 13265.96,1684.64 h60
  text "3" at 13934.96,1684.64 h60
  text "X" at 11686.02,1526.64 h60
  text "UL 94V-0" at 11822.96,1526.64 h60
  text "X" at 12498.02,1526.64 h60
  text "RoHS" at 12634.96,1526.64 h60
  text "OTHER" at 13279.36,1526.64 h60
  text "PER ORDER" at 13676.42,1526.64 h60
  text "ADDITIONAL REQUIREMENTS:" at 11332.46,1385.64 h60
  text "X" at 13930.29,1299.48 h60
  text "VIA TENTING:" at 12807,1292.36 h60
  text "YES" at 13378.67,1283.28 h60
  text "NO" at 13773.47,1283.05 h60
  text "MICROSECTION:" at 11407.23,1270.64 h60
  text "YES" at 12312.96,1270.64 h60
  text "REQUIRED" at 13174.46,1114.49 h60
  text "BARE BOARD ELEC. TEST:" at 11407.23,1111.64 h60
  text "NONE" at 12712.96,1111.64 h60
  text "X" at 13047.46,1111.64 h60
  text "PER ORDER" at 13766.46,1111.64 h60
  text "MANUFACTURER'S UL:" at 11407.23,954.64 h60
  text "RAIL" at 12572.96,950.35 h60
  text "METAL" at 13064.77,950.35 h60
  text "X" at 13440,950 h60
  text "SILK" at 13576.46,950.35 h60
M11 Gerber Information:
  lines w10: -292,-930.17 6308,-930.17 ; -292,-726.83 6310,-726.83 ; -292,-523.5 -292,-1133.5 3713,-1133.5 6310,-1133.5 6310,-523.5 -291.5,-523.5 -291.5,-1133.5 1284,-1133.5 ; 2173,-1133.5 2173,-523.5 ; 3690,-730 3690,-526.67 ; 4280,-726.83 4280,-523.5 ; 4902,-1140 4902,-937.17
  text "ALL ARTWORK VIEWED FROM TOP SIDE" at -228.5,-655.67 h60
  text "BOARD #:" at 2248,-655.67 h60
  text "TIDA-00557" at 2788,-656 h60
  text "SVN REV:" at 4476,-655.67 h60
  text ".VersionControl_RevNumber" at 4982,-655.67 h60
  text "REV: A0" at 3785,-657 h60
  text "LAYER NAME =" at -228.5,-858.49 h60
  text "PLOT NAME =" at -228.5,-1064.34 h60
  text ".plot_File_Name" at 577,-1064.34 h60
  text "GENERATED    :" at 2250,-1064.34 h60
  text ".Print_Date" at 3119.5,-1064.34 h60
  text ".Print_Time" at 3848.5,-1064.34 h60
  text "TEXAS INSTRUMENTS" at 5113,-1064.34 h60
M12 Stackup:
  lines w6: 11304,7657.5 14205,7657.5 ; 11304,7766 14205,7766 ; 11244,6974 ccw(c11279,6974) 11279,6939 14230,6939 ccw(c14230,6974) 14265,6974 14265,7858 ccw(c14230,7858) 14230,7893 11279,7893 ccw(c11279,7858) 11244,7858 11244,6974
  text "Layer Stack Up Detail for: TIDA-00557.PcbDoc" at 11304,7794.1 h48
  text "Layer" at 11304,7725.5 h25
  text "Gerber" at 12317.81,7725.5 h25
  text "Copper" at 12992.59,7725.5 h25
  text "Dielectric" at 13708.19,7725.5 h25
  text "Name" at 11304,7675.5 h25
  text "Document" at 12317.81,7675.5 h25
  text "Thickness" at 12992.59,7675.5 h25
  text "Material" at 13708.19,7675.5 h25
  text "Top Solder Mask" at 11304,7604.81 h35
  text "(.GTS)" at 12317.81,7604.81 h35
  text "Solder Resist" at 13708.19,7604.81 h35
  text "Top Layer" at 11304,7505.44 h35
  text "(.GTL)" at 12317.81,7505.44 h35
  text "1.4mil" at 12992.59,7505.44 h35
  text "FR-408" at 13726,7504 h35
  text "FR-408" at 13729,7436 h35
  text "1.4mil" at 12996,7424 h35
  text "(.GBL)" at 12324,7415 h35
  text "Bottom Layer" at 11310,7398 h35
  text "Solder Resist" at 13715,7358 h35
  text "(.GBS)" at 12326,7336 h35
  text "Bottom Solder Mask" at 11307,7313 h35
M13 Component Bodies Top:
  text ".Layer_Name" at 577,-858.49 h60
M14 Component Bodies Bottom:
  text ".Layer_Name" at 577,-858.49 h60
M15 Courtyards Top:
  text ".Layer_Name" at 577,-858.49 h60
M16 Courtyards Bottom:
  text ".Layer_Name" at 577,-858.49 h60
Drill Drawing:
  text ".legend" at 4281.25,609.45 h60
  text "Drill Table" at 4280,455 h60
  text "FOR PTH DRILL +/-3MIL" at 4295,291 h60
  text "FOR NPTH DRILL +/-2MIL" at 4295,167 h60
  text "FOR 12MIL DRILL +0/-12MIL" at 4294,37 h60
  text "FOR 16MIL DRILL +0/-16MIL" at 4298,-86 h60
  text ".Layer_Name" at 577,-858.49 h60

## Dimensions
0,0 to 0,3500 on M6 Assembly Bottom
0,3500 to 3556,3500 on M2 Board Dimensions
0,0 to 0,3500 on M2 Board Dimensions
